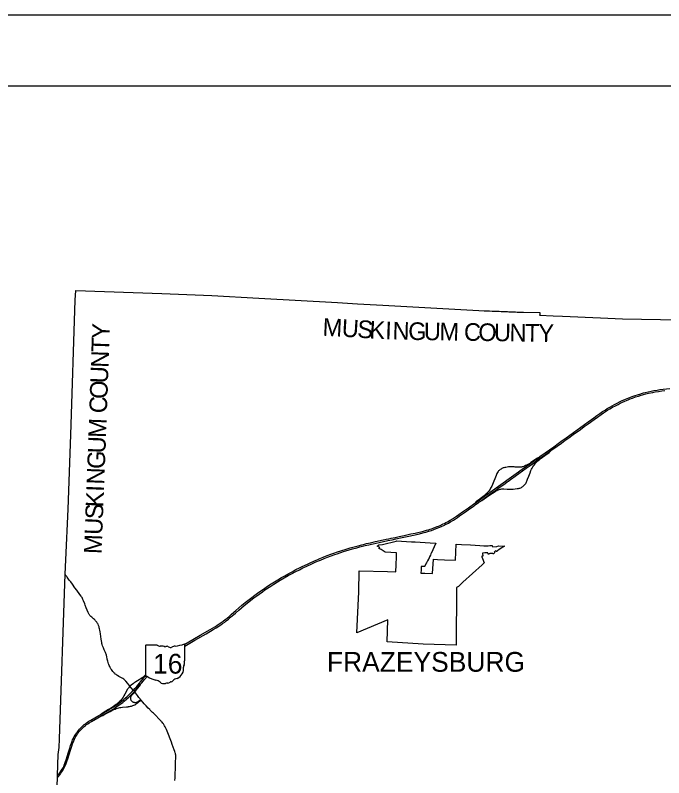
# Model space of a CAD drawing. Extents: x 2015843 to 2287843, y 623733 to 799733.
# Drawn here: x 2067453 to 2104221, y 756520 to 799733 of the extents above; entities that cross this region are included whole.
import ezdxf

# ---------------------------------------------------------------- set-up
doc = ezdxf.new("R2010")
doc.units = 0
for name, color, linetype in [('GM_X_Corporation', 7, 'Continuous'), ('GM_X_Corporation_Text', 7, 'Continuous'), ('GM_X_County', 7, 'Continuous'), ('GM_X_County_Text', 7, 'Continuous'), ('GM_X_State_Location', 7, 'Continuous'), ('GM_X_State_Route', 7, 'Continuous'), ('GM_X_State_Shield', 7, 'Continuous'), ('SH_Border', 7, 'Continuous'), ('SH_Cut_Line', 7, 'Continuous'), ('UT_P_Electric', 7, 'Continuous')]:
    doc.layers.add(name, color=color, linetype=linetype)

msp = doc.modelspace()

# ---------------------------------------------------------------- linework, layer by layer
at = {"layer": 'GM_X_Corporation'}
msp.add_lwpolyline([(2090451, 768115), (2090675, 768106), (2091108, 768088), (2091160, 768909), (2091385, 768898), (2091790, 768878), (2092405, 768847), (2092449, 769752), (2092753, 769737), (2093255, 769712), (2093802, 769685), (2094019, 769672), (2094081, 769669), (2094163, 769666), (2094214, 769665), (2094272, 769668), (2094356, 769677), (2094485, 769685), (2094507, 769605), (2094764, 769634), (2094846, 769670), (2095194, 769643), (2095191, 769641), (2095189, 769640), (2095187, 769639), (2095184, 769637), (2095180, 769635), (2095177, 769633), (2095173, 769631), (2095169, 769629), (2095166, 769627), (2095162, 769625), (2095159, 769624), (2095155, 769622), (2095152, 769620), (2095148, 769618), (2095145, 769616), (2095142, 769614), (2095138, 769612), (2095135, 769610), (2095131, 769608), (2095128, 769606), (2095124, 769604), (2095121, 769602), (2095120, 769601), (2095117, 769600), (2095114, 769598), (2095110, 769596), (2095107, 769594), (2095103, 769592), (2095100, 769590), (2095096, 769588), (2095093, 769586), (2095090, 769584), (2095086, 769582), (2095083, 769580), (2095079, 769578), (2095076, 769576), (2095072, 769574), (2095069, 769572), (2095065, 769570), (2095062, 769568), (2095059, 769565), (2095055, 769563), (2095052, 769561), (2095048, 769559), (2095045, 769557), (2095042, 769555), (2095038, 769553), (2095035, 769551), (2095031, 769549), (2095028, 769547), (2095025, 769544), (2095021, 769542), (2095018, 769540), (2095014, 769538), (2095011, 769536), (2095008, 769534), (2095004, 769532), (2095000, 769529), (2094996, 769527), (2094993, 769525), (2094990, 769523), (2094986, 769520), (2094983, 769518), (2094979, 769516), (2094976, 769514), (2094973, 769512), (2094969, 769510), (2094966, 769508), (2094963, 769505), (2094959, 769503), (2094956, 769501), (2094953, 769499), (2094949, 769497), (2094946, 769495), (2094942, 769492), (2094939, 769490), (2094936, 769488), (2094932, 769486), (2094929, 769484), (2094926, 769481), (2094923, 769479), (2094919, 769477), (2094916, 769475), (2094913, 769472), (2094909, 769470), (2094906, 769468), (2094903, 769466), (2094899, 769463), (2094896, 769461), (2094893, 769459), (2094890, 769456), (2094886, 769454), (2094883, 769452), (2094880, 769449), (2094877, 769447), (2094873, 769445), (2094870, 769443), (2094867, 769440), (2094864, 769438), (2094860, 769435), (2094857, 769433), (2094854, 769431), (2094851, 769428), (2094848, 769426), (2094844, 769424), (2094841, 769421), (2094838, 769419), (2094835, 769416), (2094832, 769414), (2094828, 769412), (2094825, 769409), (2094822, 769407), (2094819, 769404), (2094816, 769402), (2094813, 769399), (2094809, 769397), (2094806, 769394), (2094803, 769392), (2094800, 769389), (2094797, 769387), (2094794, 769384), (2094791, 769382), (2094787, 769379), (2094784, 769377), (2094781, 769374), (2094778, 769372), (2094775, 769369), (2094772, 769367), (2094769, 769364), (2094766, 769362), (2094763, 769359), (2094760, 769357), (2094757, 769354), (2094753, 769352), (2094750, 769349), (2094747, 769346), (2094744, 769344), (2094741, 769341), (2094738, 769339), (2094735, 769336), (2094731, 769333), (2094687, 769377), (2094612, 769312), (2094639, 769281), (2094562, 769203), (2094558, 769205), (2094555, 769207), (2094551, 769208), (2094548, 769210), (2094544, 769212), (2094540, 769213), (2094536, 769214), (2094533, 769216), (2094529, 769217), (2094525, 769218), (2094521, 769220), (2094517, 769221), (2094514, 769222), (2094510, 769223), (2094506, 769224), (2094502, 769225), (2094498, 769226), (2094494, 769226), (2094490, 769227), (2094486, 769228), (2094482, 769229), (2094478, 769229), (2094474, 769230), (2094470, 769230), (2094466, 769231), (2094462, 769231), (2094458, 769231), (2094454, 769232), (2094450, 769232), (2094446, 769232), (2094442, 769232), (2094438, 769232), (2094434, 769232), (2094431, 769232), (2094427, 769232), (2094423, 769232), (2094419, 769232), (2094415, 769232), (2094411, 769231), (2094407, 769231), (2094403, 769231), (2094399, 769230), (2094395, 769230), (2094391, 769229), (2094387, 769228), (2094383, 769228), (2094379, 769227), (2094375, 769226), (2094371, 769225), (2094367, 769224), (2094363, 769223), (2094359, 769222), (2094356, 769221), (2094352, 769220), (2094348, 769219), (2094344, 769218), (2094340, 769216), (2094337, 769215), (2094333, 769214), (2094329, 769212), (2094327, 769212), (2094325, 769211), (2094322, 769209), (2094315, 769207), (2094312, 769205), (2094308, 769203), (2094305, 769201), (2094301, 769199), (2094298, 769198), (2094294, 769196), (2094290, 769194), (2094287, 769192), (2094283, 769191), (2094279, 769189), (2094276, 769187), (2094272, 769186), (2094269, 769184), (2094268, 769184), (2094248, 769267), (2094074, 769267), (2093939, 769244), (2093962, 769085), (2093903, 769072), (2093907, 769031), (2093944, 768940), (2094043, 768692), (2093935, 768594), (2092835, 767601), (2092580, 767365), (2092479, 767294), (2092479, 767294), (2092455, 764039), (2090584, 764096), (2088537, 764215), (2088582, 765461), (2086820, 764727), (2086932, 767051), (2086954, 768249), (2088555, 768201), (2089023, 768183), (2089041, 768582), (2089061, 769039), (2089071, 769274), (2088428, 769311), (2088198, 769446), (2088072, 769514), (2088123, 769568), (2088052, 769606), (2087981, 769644), (2087976, 769648), (2088069, 769725), (2088076, 769726), (2088082, 769728), (2088281, 769735), (2089051, 769936), (2089070, 769940), (2089924, 769893), (2090119, 769882), (2091265, 769819), (2091293, 769818), (2091027, 769228), (2091023, 769218), (2090987, 769133), (2090947, 769039), (2090920, 768978), (2090916, 768968), (2090914, 768965), (2090913, 768961), (2090911, 768958), (2090911, 768956), (2090909, 768952), (2090907, 768948), (2090906, 768945), (2090904, 768942), (2090902, 768938), (2090900, 768935), (2090898, 768930), (2090896, 768927), (2090895, 768924), (2090893, 768921), (2090890, 768916), (2090888, 768912), (2090886, 768908), (2090882, 768903), (2090832, 768814), (2090769, 768701), (2090768, 768700), (2090761, 768687), (2090758, 768684), (2090755, 768678), (2090752, 768673), (2090749, 768669), (2090746, 768664), (2090743, 768659), (2090741, 768655), (2090739, 768652), (2090738, 768650), (2090733, 768642), (2090729, 768636), (2090726, 768631), (2090723, 768625), (2090720, 768620), (2090718, 768615), (2090715, 768611), (2090713, 768606), (2090711, 768601), (2090708, 768596), (2090705, 768591), (2090703, 768587), (2090701, 768582), (2090699, 768578), (2090696, 768572), (2090694, 768567), (2090692, 768562), (2090689, 768557), (2090687, 768553), (2090685, 768547), (2090682, 768540), (2090680, 768535), (2090678, 768531), (2090676, 768526), (2090671, 768514), (2090670, 768510), (2090668, 768506), (2090667, 768503), (2090665, 768498), (2090665, 768496), (2090664, 768494), (2090663, 768491), (2090467, 768500), (2090461, 768368), (2090459, 768300)], close=True, dxfattribs=at)
at = {"layer": 'GM_X_County'}
msp.add_lwpolyline([(2069607, 750462), (2069850, 756543), (2069853, 756656), (2069894, 757841), (2069935, 758229), (2069959, 758723), (2070278, 768051), (2070323, 768867), (2070448, 771746), (2070609, 775946), (2070855, 783589), (2070892, 784141), (2075761, 783968), (2078590, 783843), (2081257, 783694), (2085728, 783453), (2086861, 783383), (2088289, 783309), (2093740, 783008), (2094035, 782985), (2094106, 782985), (2094337, 782976), (2094488, 782969), (2094603, 782966), (2094685, 782962), (2094750, 782959), (2094881, 782955), (2095012, 782953), (2095111, 782950), (2095242, 782945), (2095356, 782939), (2095438, 782934), (2095573, 782928), (2095747, 782920), (2095812, 782918), (2095815, 782918), (2095910, 782915), (2096008, 782912), (2096189, 782906), (2096240, 782904), (2096257, 782902), (2096267, 782900), (2096273, 782897), (2097198, 782879), (2097195, 782802), (2097194, 782787), (2097189, 782758), (2097184, 782735), (2097949, 782707), (2098487, 782682), (2100643, 782587), (2101884, 782528), (2105109, 782463)], dxfattribs=at)
at = {"layer": 'GM_X_State_Route'}
for points in [[(2072992, 762537), (2072988, 762542), (2072947, 762593), (2072908, 762646), (2072874, 762699), (2072838, 762762), (2072809, 762816), (2072775, 762890), (2072756, 762935), (2072739, 762982), (2072719, 763044), (2072698, 763123), (2072683, 763187), (2072674, 763235), (2072667, 763267), (2072645, 763379), (2072626, 763458), (2072608, 763521), (2072592, 763566), (2072567, 763627), (2072540, 763685), (2072496, 763773), (2072475, 763818), (2072449, 763878), (2072431, 763923), (2072404, 764001), (2072385, 764064), (2072370, 764127), (2072357, 764191), (2072340, 764288), (2072324, 764379), (2072302, 764522), (2072279, 764680), (2072261, 764794), (2072246, 764891), (2072234, 764955), (2072219, 765019), (2072206, 765066), (2072190, 765112), (2072173, 765157), (2072146, 765216), (2072124, 765260), (2072099, 765302), (2072072, 765343), (2072043, 765382), (2072010, 765420), (2071977, 765456), (2071942, 765489), (2071893, 765532), (2071794, 765616), (2071745, 765660), (2071710, 765695), (2071688, 765718), (2071664, 765746), (2071643, 765779), (2071621, 765816), (2071588, 765884), (2071481, 766145), (2071424, 766297), (2071394, 766374), (2071328, 766541), (2071290, 766631), (2071269, 766676), (2071240, 766733), (2071215, 766776), (2071189, 766817), (2071123, 766910), (2070938, 767159), (2070840, 767291), (2070694, 767488), (2070597, 767620), (2070518, 767725), (2070440, 767830), (2070401, 767883), (2070373, 767922), (2070354, 767948), (2070324, 767987), (2070279, 768048)], [(2074244, 761355), (2074225, 761379), (2074206, 761404), (2074164, 761456), (2074148, 761476), (2074051, 761597), (2073958, 761710), (2073833, 761861), (2073716, 761998), (2073673, 762043), (2073640, 762075), (2073607, 762102), (2073562, 762136), (2073509, 762170), (2073444, 762207), (2073332, 762266), (2073260, 762306), (2073206, 762339), (2073166, 762368), (2073126, 762398), (2073091, 762429), (2073052, 762466), (2073021, 762502), (2072992, 762537)], [(2075142, 760317), (2075100, 760359), (2075076, 760383), (2074996, 760465), (2074872, 760594), (2074762, 760716), (2074679, 760812), (2074587, 760925), (2074564, 760953), (2074530, 760994), (2074469, 761070), (2074378, 761186), (2074266, 761328), (2074244, 761355)], [(2076532, 756984), (2076548, 757385), (2076557, 757677), (2076558, 757728), (2076555, 757779), (2076552, 757814), (2076548, 757845), (2076539, 757892), (2076527, 757940), (2076507, 758002), (2076469, 758110), (2076352, 758413), (2076303, 758535), (2076058, 759159), (2076022, 759250), (2075990, 759326), (2075955, 759399), (2075916, 759471), (2075883, 759528), (2075854, 759569), (2075815, 759620), (2075777, 759667), (2075751, 759698), (2075720, 759733), (2075284, 760174), (2075239, 760220), (2075146, 760313), (2075142, 760317)], [(2076507, 756363), (2076513, 756522), (2076524, 756801), (2076532, 756984)]]:
    msp.add_lwpolyline(points, dxfattribs=at)
at = {"layer": 'GM_X_State_Shield'}
for p, q in [((2075507, 764030), (2074851, 764030)), ((2077070, 763183), (2077070, 764073)), ((2074829, 764001), (2074829, 762300)), ((2077070, 763183), (2077070, 763183))]:
    msp.add_line(p, q, dxfattribs=at)
for centre, radius, start, end in [((2074855, 764005), 26, 98.1301, 188.1301), ((2075664, 764228), 252, 231.6195, 271.1119), ((2076272, 766350), 2377, 275.8445, 288.9065), ((2077046, 764076), 25, 351.8621, 97.738), ((2075747, 763075), 904, 80.4867, 94.9883), ((2075953, 764014), 72.7, 219.7921, 297.1024), ((2076059, 763817), 151, 54.4667, 119.1411), ((2076254, 764087), 182, 233.8562, 294.8282), ((2076575, 763511), 478, 97.3462, 120.7689), ((2077065, 763117), 38.6, 107.944, 210.337), ((2077044, 763179), 26.7, 289.6038, 7.7341), ((2076405, 762697), 595, 292.3089, 8.9858), ((2077160, 762810), 169, 136.8065, 186.9296), ((2076819, 763005), 232, 340.033, 23.6496), ((2074855, 762296), 26.2, 171.9584, 258.3066), ((2074859, 762470), 200, 267.339, 280.6039), ((2074900, 762202), 72.1, 29.7484, 93.2717), ((2075810, 763730), 1716, 240.4129, 257.1985), ((2075298, 761536), 537, 47.1842, 75.836), ((2075879, 762193), 341, 230.7004, 286.2918), ((2076076, 761605), 280, 85.6951, 111.2099), ((2076101, 762066), 182, 268.777, 315.5493), ((2076265, 761901), 51.1, 65.7517, 132.6484), ((2076243, 762135), 192, 282.8732, 323.2771), ((2076656, 761822), 326, 94.4031, 142.5768)]:
    msp.add_arc(centre, radius, start, end, dxfattribs=at)
at = {"layer": 'SH_Border'}
msp.add_lwpolyline([(2027843, 795733), (2283843, 795733), (2283843, 627733), (2027843, 627733)], close=True, dxfattribs=at)
at = {"layer": 'SH_Cut_Line'}
msp.add_lwpolyline([(2015843, 623733), (2287843, 623733), (2287843, 799733), (2015843, 799733)], close=True, dxfattribs=at)
at = {"layer": 'UT_P_Electric'}
msp.add_line((2097076, 774636), (2097196, 774722), dxfattribs=at)
for points in [[(2097196, 774722), (2097221, 774740), (2097502, 774940), (2097742, 775111), (2097982, 775283), (2098235, 775464), (2098462, 775627), (2098688, 775790), (2099315, 776239), (2099940, 776689), (2100261, 776917), (2100433, 777042), (2100594, 777156), (2100756, 777268), (2100892, 777359), (2101016, 777438), (2101156, 777523), (2101298, 777605), (2101427, 777675), (2101573, 777751), (2101720, 777823), (2101868, 777893), (2102018, 777959), (2102154, 778017), (2102291, 778071), (2102429, 778123), (2102599, 778182), (2102724, 778223), (2102928, 778285), (2102963, 778295), (2103070, 778325), (2103165, 778350), (2103340, 778392), (2103500, 778427), (2103661, 778459), (2103855, 778492), (2104001, 778514), (2104179, 778537), (2104571, 778580)], [(2097827, 775064), (2097929, 775136), (2098182, 775318), (2098420, 775491), (2098634, 775644), (2098834, 775787), (2099087, 775969), (2099500, 776265), (2099713, 776418), (2099940, 776579), (2100273, 776819), (2100459, 776953), (2100673, 777105), (2100808, 777199), (2100917, 777272), (2101027, 777343), (2101168, 777428), (2101324, 777518), (2101482, 777605), (2101627, 777681), (2101759, 777747), (2101878, 777803), (2102013, 777863), (2102195, 777939), (2102316, 777987), (2102455, 778039), (2102625, 778099), (2102781, 778151), (2102937, 778200), (2103022, 778224), (2103079, 778241), (2103206, 778274), (2103350, 778307), (2103607, 778361), (2103736, 778385), (2103914, 778414), (2104109, 778441), (2104289, 778463)], [(2095568, 772870), (2095643, 772870), (2095675, 772872), (2095919, 772906), (2095984, 772917), (2096032, 772928), (2096064, 772938), (2096110, 772955), (2096154, 772976), (2096197, 773001), (2096238, 773029), (2096276, 773060), (2096312, 773094), (2096345, 773130), (2096375, 773169), (2096394, 773196), (2096419, 773239), (2096442, 773283), (2096462, 773328), (2096503, 773435), (2096573, 773620), (2096644, 773804), (2096693, 773926), (2096726, 774001), (2096755, 774060), (2096795, 774132), (2096829, 774188), (2096866, 774243), (2096905, 774296), (2096947, 774346), (2096991, 774395), (2097038, 774441), (2097086, 774485), (2097150, 774538), (2097214, 774588), (2097476, 774781), (2097716, 774958), (2097753, 774985), (2097803, 775026), (2097815, 775040), (2097827, 775064)], [(2097287, 774680), (2097541, 774860), (2097728, 774994), (2097827, 775064)], [(2077067, 764090), (2077517, 764351), (2077941, 764600), (2078509, 764929), (2078764, 765078), (2078890, 765155), (2079014, 765235), (2079122, 765309), (2079242, 765396), (2079359, 765486), (2079462, 765568), (2079574, 765664), (2079696, 765770), (2079723, 765793), (2079956, 765999), (2080131, 766148), (2080307, 766296), (2080497, 766451), (2080638, 766564), (2080859, 766734), (2081029, 766862), (2081188, 766978), (2081322, 767073), (2081524, 767213), (2081755, 767369), (2081961, 767503), (2082155, 767625), (2082336, 767737), (2082548, 767862), (2082732, 767969), (2082961, 768097), (2083148, 768199), (2083366, 768313), (2083570, 768418), (2083717, 768491), (2084014, 768631), (2084208, 768718), (2084508, 768850), (2084605, 768891), (2084719, 768939), (2084917, 769019), (2085146, 769109), (2085345, 769184), (2085515, 769245), (2085731, 769321), (2085918, 769382), (2086263, 769490), (2086435, 769542), (2086672, 769610), (2086893, 769671), (2087100, 769724), (2087195, 769747), (2087371, 769789), (2087476, 769812), (2087594, 769839), (2087883, 769901), (2088315, 769995), (2088491, 770034), (2088635, 770066), (2088763, 770093), (2088988, 770141), (2089228, 770192), (2089501, 770250), (2089886, 770334), (2090126, 770385), (2090287, 770419), (2090447, 770456), (2090542, 770479), (2090653, 770509), (2090779, 770545), (2090843, 770561), (2090906, 770579), (2090985, 770603), (2091062, 770630), (2091154, 770665), (2091373, 770750), (2091456, 770787), (2091539, 770823), (2091680, 770889), (2091710, 770903), (2091784, 770938), (2091872, 770983), (2091959, 771030), (2092102, 771110), (2092243, 771193), (2092355, 771263), (2092464, 771335), (2092612, 771438), (2092812, 771582), (2093145, 771821), (2093505, 772079), (2093544, 772107), (2093772, 772271), (2095595, 773575), (2095849, 773756), (2096195, 774005), (2096435, 774176), (2096622, 774309), (2096836, 774462), (2096913, 774518), (2097076, 774636)], [(2079771, 765710), (2079830, 765761), (2079933, 765851), (2080129, 766024), (2080279, 766152), (2080431, 766278), (2080597, 766411), (2080817, 766583), (2080986, 766712), (2081144, 766830), (2081277, 766926), (2081465, 767059), (2081613, 767161), (2081940, 767379), (2082119, 767495), (2082314, 767617), (2082482, 767719), (2082695, 767843), (2082923, 767973), (2083124, 768083), (2083370, 768215), (2083560, 768312), (2083765, 768415), (2083943, 768500), (2084300, 768664), (2084466, 768736), (2084639, 768809), (2084753, 768856), (2084966, 768943), (2085164, 769020), (2085364, 769095), (2085564, 769168), (2085704, 769217), (2086062, 769334), (2086376, 769432), (2086580, 769492), (2086817, 769558), (2086992, 769603), (2087294, 769679), (2087502, 769728), (2087585, 769746), (2087742, 769780), (2088079, 769853), (2088575, 769961), (2088816, 770012), (2089024, 770057), (2089393, 770136), (2089762, 770215), (2090291, 770330), (2090514, 770381), (2090642, 770414), (2090736, 770440), (2090909, 770492), (2091049, 770537), (2091188, 770586), (2091326, 770639), (2091463, 770695), (2091628, 770767), (2091648, 770777), (2091746, 770823), (2091893, 770896), (2092009, 770957), (2092152, 771037), (2092293, 771120), (2092405, 771189), (2092528, 771270), (2092649, 771355), (2092863, 771507), (2093050, 771640), (2093210, 771755), (2093463, 771936), (2093530, 771984), (2093717, 772117), (2093820, 772191), (2093837, 772203), (2094036, 772347), (2094169, 772443), (2094275, 772520), (2094583, 772738), (2094677, 772805), (2094823, 772910), (2095222, 773198), (2095343, 773283), (2095410, 773331), (2095556, 773436), (2095591, 773461), (2096421, 774059), (2096595, 774183), (2096781, 774316), (2096912, 774411), (2097034, 774499), (2097287, 774680)], [(2097076, 774636), (2097040, 774625), (2097011, 774609), (2096964, 774575), (2096913, 774539), (2096779, 774445), (2096690, 774382), (2096621, 774337), (2096551, 774295), (2096480, 774255), (2096406, 774218), (2096383, 774207)], [(2095622, 774145), (2095572, 774145), (2095549, 774145), (2095498, 774140), (2095422, 774131), (2095259, 774109), (2095210, 774101), (2095161, 774090), (2095114, 774075), (2095083, 774063), (2095038, 774041), (2094995, 774016), (2094954, 773987), (2094929, 773967), (2094897, 773940), (2094861, 773905)], [(2096383, 774207), (2096332, 774184), (2096286, 774165), (2096239, 774149), (2096192, 774137), (2096160, 774130), (2096111, 774123), (2096062, 774120), (2096013, 774120), (2095898, 774125), (2095803, 774128), (2095747, 774132), (2095703, 774137), (2095622, 774145)], [(2094861, 773905), (2094828, 773869), (2094789, 773813), (2094764, 773765), (2094718, 773646), (2094507, 773130), (2094468, 773040), (2094439, 772981), (2094407, 772923), (2094373, 772867), (2094337, 772813), (2094298, 772760), (2094256, 772709), (2094212, 772661), (2094166, 772614), (2094118, 772569), (2094056, 772516), (2093966, 772445), (2093809, 772326), (2093785, 772308), (2093612, 772178), (2093576, 772150), (2093557, 772128), (2093544, 772107)], [(2093820, 772191), (2093876, 772212), (2093913, 772234), (2094173, 772427), (2094287, 772506), (2094420, 772600), (2094503, 772654), (2094601, 772714), (2094686, 772762), (2094759, 772800), (2094769, 772805)], [(2094769, 772805), (2094803, 772822), (2094848, 772841), (2094895, 772857), (2094942, 772871), (2094990, 772881), (2095038, 772888), (2095087, 772891), (2095153, 772891), (2095349, 772883), (2095449, 772879), (2095568, 772870)], [(2077070, 763986), (2077253, 764092), (2077636, 764314), (2078274, 764685), (2078671, 764917), (2078840, 765017), (2078994, 765112), (2079103, 765184), (2079211, 765259), (2079330, 765346), (2079421, 765415), (2079536, 765508), (2079661, 765613), (2079771, 765710)], [(2069854, 756653), (2069925, 756732), (2069976, 756797), (2070024, 756863), (2070079, 756945), (2070122, 757015), (2070162, 757086), (2070199, 757160), (2070233, 757235), (2070270, 757326), (2070308, 757434), (2070359, 757590), (2070461, 757920), (2070549, 758205), (2070591, 758343), (2070638, 758483), (2070677, 758590), (2070708, 758666), (2070735, 758726), (2070763, 758785), (2070802, 758857), (2070843, 758927), (2070887, 758996), (2070933, 759064), (2070982, 759130), (2071033, 759194), (2071097, 759268), (2071164, 759340), (2071233, 759410), (2071293, 759466), (2071367, 759530), (2071430, 759582), (2071496, 759631), (2071549, 759668), (2071632, 759721), (2071745, 759789), (2072186, 760040), (2072269, 760087), (2072786, 760380), (2072913, 760455), (2073038, 760534), (2073161, 760615), (2073282, 760700), (2073401, 760788), (2073505, 760868), (2073594, 760942), (2073693, 761028), (2073790, 761116), (2073909, 761229), (2073991, 761309), (2074082, 761404), (2074148, 761476), (2074160, 761489), (2074235, 761575), (2074342, 761700), (2074705, 762144), (2074829, 762294)], [(2074829, 762343), (2074775, 762292), (2074701, 762227), (2074638, 762175), (2074586, 762136), (2074532, 762098), (2074477, 762063), (2074392, 762014), (2074292, 761957), (2074237, 761923), (2074196, 761896), (2074156, 761867), (2074028, 761765), (2073958, 761710)], [(2074191, 761388), (2074206, 761404), (2074274, 761479), (2074370, 761591), (2074557, 761818), (2074631, 761907), (2074789, 762096), (2074930, 762267)], [(2073958, 761710), (2073891, 761634), (2073868, 761606), (2073851, 761583), (2073835, 761562), (2073808, 761521), (2073777, 761464), (2073671, 761261), (2073616, 761160), (2073575, 761090), (2073539, 761035), (2073501, 760981), (2073461, 760930), (2073418, 760881), (2073373, 760833), (2073326, 760788), (2073277, 760745), (2073213, 760694), (2073120, 760626), (2073026, 760561), (2072916, 760490), (2072749, 760387), (2072434, 760191), (2072357, 760149), (2072296, 760113), (2072269, 760087)], [(2074564, 760953), (2074488, 760887), (2074451, 760854), (2074412, 760825), (2074385, 760807), (2074355, 760792), (2074340, 760786), (2074324, 760781), (2074309, 760777), (2074292, 760774), (2074276, 760772), (2074260, 760772), (2074243, 760772), (2074227, 760773), (2074211, 760776), (2074195, 760779), (2074179, 760784), (2074164, 760789), (2074148, 760796), (2074134, 760803), (2074120, 760811), (2074106, 760821), (2074093, 760831), (2074081, 760842), (2074069, 760853), (2074059, 760866), (2074049, 760879), (2074040, 760893), (2074032, 760907), (2074024, 760922), (2074013, 760952), (2074009, 760968), (2074003, 761001), (2074002, 761017), (2074003, 761050), (2074005, 761066), (2074013, 761098), (2074018, 761113), (2074031, 761143), (2074047, 761172), (2074065, 761199), (2074096, 761238), (2074128, 761275), (2074207, 761358), (2074225, 761379), (2074262, 761420), (2074317, 761487), (2074500, 761712), (2074520, 761738), (2074542, 761771), (2074550, 761789), (2074557, 761818)], [(2071262, 759334), (2071306, 759375), (2071368, 759430), (2071432, 759481), (2071497, 759530), (2071565, 759577), (2071648, 759630), (2071775, 759706), (2072131, 759910), (2072371, 760047), (2072601, 760177), (2072843, 760316), (2072999, 760407), (2073124, 760485), (2073219, 760549), (2073327, 760624), (2073445, 760712), (2073549, 760792), (2073637, 760865), (2073760, 760973), (2073894, 761094), (2074001, 761196), (2074117, 761311), (2074191, 761388)], [(2073852, 760548), (2073873, 760551), (2073938, 760560), (2073987, 760570), (2074035, 760582), (2074082, 760596), (2074128, 760613), (2074174, 760632), (2074233, 760661), (2074290, 760694), (2074331, 760722), (2074396, 760771), (2074499, 760854), (2074587, 760925)], [(2072371, 760047), (2072411, 760056), (2072469, 760088), (2072677, 760199), (2072832, 760281), (2072935, 760333), (2073039, 760381), (2073115, 760413), (2073176, 760437), (2073255, 760462), (2073318, 760480), (2073382, 760494), (2073447, 760506), (2073529, 760517), (2073758, 760538), (2073852, 760548)], [(2070383, 757444), (2070385, 757448), (2070431, 757588), (2070509, 757839), (2070600, 758137), (2070621, 758203), (2070654, 758309), (2070696, 758434), (2070730, 758526), (2070768, 758617), (2070809, 758707), (2070853, 758795), (2070894, 758866), (2070936, 758936), (2070982, 759005), (2071030, 759071), (2071080, 759136), (2071133, 759199), (2071188, 759260), (2071246, 759319), (2071262, 759334)], [(2069851, 756540), (2069998, 756713), (2070047, 756779), (2070093, 756846), (2070146, 756929), (2070187, 757000), (2070234, 757086), (2070270, 757159), (2070303, 757234), (2070340, 757325), (2070383, 757444)]]:
    msp.add_lwpolyline(points, dxfattribs=at)

# ---------------------------------------------------------------- texts
at = {"layer": 'GM_X_Corporation_Text'}
msp.add_text('FRAZEYSBURG', height=1120, rotation=0, dxfattribs=at).set_placement((2085123, 762527))
at = {"layer": 'GM_X_County_Text'}
for s, rotation, p in [('Y', 88.0873, (2072791, 781371)), ('M', 357.2115, (2084860, 781572)), ('U', 356.4278, (2085942, 781520)), ('S', 356.4112, (2086824, 781464)), ('K', 357.0853, (2087513, 781421)), ('I', 358.1377, (2088417, 781376)), ('N', 358.4214, (2088831, 781362)), ('G', 358.9475, (2089725, 781338)), ('U', 359.1434, (2090613, 781321)), ('M', 359.1871, (2091498, 781308)), ('C', 359.1883, (2092889, 781288)), ('O', 359.1883, (2093702, 781277)), ('U', 359.1877, (2094587, 781264)), ('N', 359.1883, (2095471, 781252)), ('T', 359.1887, (2096355, 781239)), ('Y', 359.1883, (2097103, 781229)), ('T', 88.0873, (2072766, 780625)), ('N', 88.0714, (2072736, 779743)), ('U', 88.0411, (2072706, 778860)), ('O', 88.001, (2072675, 777977)), ('C', 87.9537, (2072646, 777162)), ('M', 87.9381, (2072596, 775770)), ('U', 87.8907, (2072564, 774887)), ('G', 87.85, (2072530, 774004)), ('N', 87.8204, (2072497, 773122)), ('K', 87.7997, (2072447, 771832)), ('I', 87.807, (2072481, 772715)), ('S', 87.7976, (2072421, 771153)), ('U', 87.7975, (2072387, 770271)), ('M', 87.7975, (2072346, 769185))]:
    msp.add_text(s, height=1000, rotation=rotation, dxfattribs=at).set_placement(p)
at = {"layer": 'GM_X_State_Location'}
for s, p in [('16', (2098208, 775324)), ('16', (2075337, 762784)), ('586', (2075979, 758454))]:
    msp.add_text(s, height=1, rotation=0, dxfattribs=at).set_placement(p)
for s, p in [('s', (2098460, 775397)), ('r', (2098460, 775397)), ('s', (2075589, 762857)), ('r', (2075589, 762857)), ('s', (2076332, 758527)), ('r', (2076332, 758527))]:
    msp.add_text(s, height=1, dxfattribs=at).set_placement(p)
at = {"layer": 'GM_X_State_Shield'}
msp.add_text('16', height=1120.7, dxfattribs=at).set_placement((2075267, 762420))

doc.saveas('drawing.dxf')
